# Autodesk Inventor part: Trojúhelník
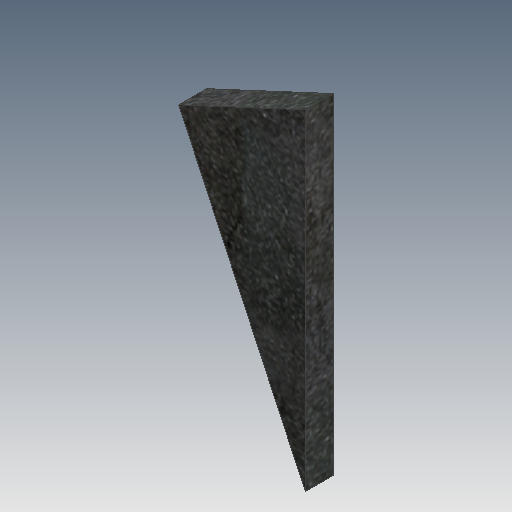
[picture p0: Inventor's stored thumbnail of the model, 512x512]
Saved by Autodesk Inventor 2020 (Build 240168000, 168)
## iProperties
Created: 2025-03
Part Number: Trojúhelník
Material: Ocel
Document SubType Name: Modeling
Designer: doma
Density: 7.85 g/cm^3
Appearance: Plech
Mass: 107.74 g
Surface Area: 51.9464 cm^2
Volume: 13.7248 cm^3
Author: doma
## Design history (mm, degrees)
sketch "Náčrt1"
  geometry: L1 (1893.939, -93.847)-(1857.686, -16.104); L2 (1893.939, 0.801)-(1857.686, -16.104); L3 (1893.939, 0.801)-(1893.939, -93.847); 3 further points
  constraints: 6 end point
extrude "Vysunutí1" new body sketch "Náčrt1" distance "d54" = 8; taper "d55" = 0 deg
node "Těleso1"
